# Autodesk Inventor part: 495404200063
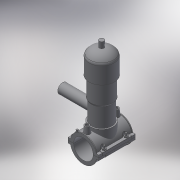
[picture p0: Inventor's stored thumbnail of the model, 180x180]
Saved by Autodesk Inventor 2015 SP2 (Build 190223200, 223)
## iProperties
Created: 2017-07
Part Number: 495404200063
Material: Generic
Description: PLASSON TAPPING VALVE 200-63
Document SubType Name: Modeling
Designer: KIM
Density: 1 g/cm^3
Appearance: Default
Author: KIM
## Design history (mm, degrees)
derived "495404-4954S4.ipt"
feature "Solid1::495404-4954S4.ipt"
feature "Solid2::495404-4954S4.ipt"
tag "TaggingFeature1"
body "Solid1"
body "Solid2"
other parameters: "d2" = 262.6, "d4" = 176, "d5" = 0, "d6" = 0.1, "d8" = 0, "d19" = 6, "d20" = 6, "d21" = 105.6, "d23" = 0, "d24" = 52.8, "d26" = 0, "d27" = 3, "d28" = 3, "d29" = 3, "d30" = 66.66667, "d31" = 6, "d32" = 0, "d33" = 0, "d34" = 0.6, "d40" = 121.68, "d47" = 168, "d70" = 15, "d72" = 0, "d73" = 6, "d75" = 5, "d76" = 0, "d79" = 15, "d80" = 70.4, "d82" = 5 deg, "d84" = 4, "d85" = 14, "d86" = 0, "d87" = 3, "d88" = 0, "d89" = 1, "d90" = 1, "d91" = 140.8, "d92" = 0, "d93" = 0.5, "d94" = 105.26316, "d96" = 241.02, "d97" = 3.52, "d98" = 0, "d120" = 140 deg, "d121" = 24.228, "d122" = 20 deg, "d123" = 468, "d124" = 140.4, "d126" = 0, "d143" = 206, "d145" = 26.15385, "d149" = 3, "d150" = 28.76923, "d153" = 176, "d154" = 0, "d156" = 117, "d157" = 160 deg, "d159" = 6.8, "d161" = 3, "d162" = 105.6, "d163" = 0, "d168" = 114.14634, "d170" = 3, "d172" = 0, "d173" = 1, "d176" = 20 deg, "d177" = 14, "d178" = 34, "d180" = 0, "d183" = 13.6, "d184" = 11.2, "d185" = 57.2, "d186" = 57.2, "d187" = 117, "d188" = 10.2, "d189" = 14, "d190" = 0, "d191" = 175.5, "d193" = 6.8, "d194" = 4.4, "d195" = 90 deg, "d197" = 0, "d199" = 0, "d205" = 14.64, "d206" = 81.33333, "d207" = 244, "d208" = 224.48, "d209" = 207.4, "d210" = 200.08, "d211" = 146.4, "d212" = 85.4, "d213" = 65.88, "d214" = 73.2, "d216" = 21.96, "d217" = 70.76, "d218" = 80.52, "d222" = 0, "d223" = 234, "d224" = 186, "d225" = 51, "d226" = 63, "d229" = 186, "d230" = 0, "B_" = 202, "H_" = 186, "L_" = 176, "d_t" = 6, "d_1" = 63, "H_1" = 51, "H_2" = 244, "d148" = 3, "d160" = 3, "d169" = 3, "d192" = 6.8, "d228" = 50.4
